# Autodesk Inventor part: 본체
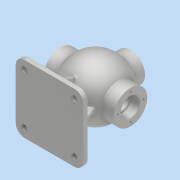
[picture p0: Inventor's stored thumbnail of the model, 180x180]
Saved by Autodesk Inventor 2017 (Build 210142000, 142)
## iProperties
Part Number: 본체
Material: 알루미늄 6061
Document SubType Name: Modeling
Designer: MRC
Density: 2.7 g/cm^3
Appearance: 알루미늄 - 평지
Mass: 1457.53 g
Surface Area: 1170.28 cm^2
Volume: 539.828 cm^3
Author: MRC
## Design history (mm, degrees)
sketch "스케치1"
  geometry: L1 (0, 53)-(0, -53); A1 r 53 centre (0, 0) between (0, -53) and (0, 53); 2 further points
  constraints: 2 coincident, 2 end point, 2 point on circle, 1 centre point, 1 midpoint, 1 vertical
  dimensions: "d2" = 106 diameter of A1
revolve "회전1" sketch "스케치1" stored, may be unused: angle "d3" = 90 deg
sketch "스케치2"
  geometry: L1 (0, 44)-(0, -44); A1 r 44 centre (0, 0) between (0, -44) and (0, 44); 2 further points
  constraints: 2 coincident, 2 end point, 2 point on circle, 1 centre point, 1 midpoint, 1 vertical
  dimensions: "d4" = 88 distance of L1.start L1.end
revolve "회전2" sketch "스케치2" stored, may be unused: angle "d5" = 90 deg
node "작업 평면1"
sketch "스케치3"
  geometry: C1 r 31 at (0, 0); 1 further point
  constraints: 1 centre point, 1 coincident
  dimensions: "d7" = 62 diameter of C1
extrude "돌출1" join sketch "스케치3" stored distance "d8" = 16; taper "d9" = 0 deg
sketch "스케치4"
  geometry: C1 r 17.5 at (0, 0); 1 further point
  constraints: 1 centre point, 1 coincident
  dimensions: "d10" = 35 diameter of C1
extrude "돌출2" cut sketch "스케치4" distance "d11" = 16; taper "d12" = 0 deg
sketch "스케치5"
  geometry: C1 r 15 at (0, 0); 1 further point
  constraints: 1 centre point, 1 coincident
  dimensions: "d13" = 30 diameter of C1
extrude "돌출3" cut sketch "스케치5" stored distance "d14" = 16; taper "d15" = 0 deg
fillet "모깎기1" dims "d16" = 0.6
chamfer "모따기1" distance "d17" = 1; stored, may be unused: second distance "d18" = 2, angle "d19" = 45 deg
sketch "스케치7"
  geometry: L1 (-62.5, -75)-(62.5, -75); L2 (62.5, -75)-(62.5, -85); L3 (62.5, -85)-(-62.5, -85); L4 (-62.5, -85)-(-62.5, -75); 2 further points
  constraints: 8 end point, 2 parallel, 1 horizontal, 1 midpoint, 1 perpendicular, 1 vertical alignment
  dimensions: "d20" = 125 distance of L1.start L1.end; "d21" = 10 distance of L1.end L2.end; "d22" = 85 distance from line of L3 point (0, 0)
extrude "돌출4" join sketch "스케치7" stored distance "d23" = 125; taper "d24" = 0 deg
sketch "스케치8"
  geometry: L1 (50.5, -75)-(39.971, -46.072); L2 (-50.5, -75)-(-41.337, -49.825); L3 (-62.5, -75)-(62.5, -75) reference; L4 (62.5, -75)-(62.5, -85) reference; L5 (-62.5, -85)-(-62.5, -75) reference; 1 further point
  constraints: 4 end point, 2 point on line
  dimensions: "d25" = 12 distance from line of L4 L1.start; "d26" = 12 distance of L3.start L2.start; "d28" = 20 deg angle of L1 L4; "d29" = 20 deg angle of L2 L5
feature "리브1" dims "d30" = 40, "d31" = 8, "d32" = 0, "d33" = 0, "d34" = 1, "d35" = 1
feature "리브2" dims "d36" = 40, "d37" = 8, "d38" = 0, "d39" = 0, "d40" = 1, "d41" = 1
sketch "스케치9"
  geometry: L1 (-75, 50.5)-(-46.657, 40.184); L2 (-75, -50.5)-(-48.7, -40.928); L3 (-75, -62.5)-(-85, -62.5) reference; L4 (-85, 62.5)-(-75, 62.5) reference; L5 (-85, 62.5)-(-85, -62.5) reference; L6 (-75, -62.5)-(-85, -62.5) reference; L7 (-75, 62.5)-(-75, -62.5) reference; L8 (-85, 62.5)-(-75, 62.5) reference; 1 further point
  constraints: 4 end point, 2 point on line
  dimensions: "d42" = 20 deg angle of L1 L4; "d43" = 20 deg angle of L2 L3; "d44" = 12 distance of L3.start L2.start; "d45" = 12 distance of L4.end L1.start
  node "투영된 루프1"
feature "리브3" dims "d46" = 40, "d47" = 8, "d48" = 0, "d49" = 0, "d50" = 1, "d51" = 1
feature "리브4" dims "d52" = 40, "d53" = 8, "d54" = 0, "d55" = 0, "d56" = 1, "d57" = 1
fillet "모깎기2" dims "d58" = 3
fillet "모깎기3" dims "d59" = 3
fillet "모깎기4" dims "d60" = 3
fillet "모깎기5" dims "d61" = 16
node "작업 평면2"
sketch "스케치10"
  geometry: C1 r 27 at (0, 0); 1 further point
  constraints: 1 centre point, 1 coincident
  dimensions: "d63" = 54 diameter of C1
extrude "돌출5" join sketch "스케치10" stored distance "d64" = 125; taper "d65" = 0 deg
sketch "스케치11"
  geometry: C1 r 13 at (0, 0); 1 further point
  constraints: 1 centre point, 1 coincident
  dimensions: "d66" = 26 diameter of C1
extrude "돌출6" cut sketch "스케치11" stored distance "d67" = 125; taper "d68" = 0 deg
fillet "모깎기6" dims "d69" = 3
sketch "스케치12"
  geometry: 2 further points
  constraints: 1 vertical alignment
  dimensions: "d70" = 24 distance of point (0, 0) point (0, 24)
hole "구멍1" sketch "스케치12" at (0, 24) diameter "d71" = 3.242; stored, may be unused: countersink angle "d75" = 90 deg, drill point angle "d77" = 118 deg; dims "d72" = 12, "d73" = 4, "d74" = 2, "d76" = 15
sketch "스케치13"
  geometry: 2 further points
  constraints: 1 vertical alignment
  dimensions: "d81" = 20 distance of point (0, 20) point (0, 0)
hole "구멍2" sketch "스케치13" at (0, 20) diameter "d82" = 3.242; stored, may be unused: countersink angle "d86" = 90 deg, drill point angle "d88" = 118 deg; dims "d83" = 9, "d84" = 4, "d85" = 2, "d87" = 11
sketch "스케치14"
  geometry: L1 (-16, 16)-(-16, 109) reference; L2 (93, 125)-(0, 125) reference; L3 (109, 16)-(109, 109) reference; L4 (0, 0)-(93, 0) reference; C1 r 5.5 at (0, 109); C2 r 5.5 at (0, 16); C3 r 5.5 at (93, 109); C4 r 5.5 at (93, 16); A1 r 16 centre (0, 16) between (-16, 16) and (0, 0) reference; A2 r 16 centre (0, 109) between (0, 125) and (-16, 109) reference; A3 r 16 centre (93, 109) between (109, 109) and (93, 125) reference; A4 r 16 centre (93, 16) between (93, 0) and (109, 16) reference; 1 further point
  constraints: 4 centre point, 4 coincident
  dimensions: "d92" = 11 diameter of C1; "d93" = 11 diameter of C2; "d94" = 11 diameter of C3; "d95" = 11 diameter of C4
extrude "돌출7" cut sketch "스케치14" distance "d96" = 125; taper "d97" = 0 deg
fillet "모깎기7" dims "d98" = 3
fillet "모깎기8" dims "d99" = 3
node "작업 평면3"
sketch "스케치15"
  geometry: L1 (1.621, 54)-(1.621, 65) reference; L2 (-27, 65)-(27, 65) reference; L3 (-27, 47.286)-(27, 47.286) reference; L4 (-42.113, 32.179)-(-42.113, -32.179) reference; L5 (-6.625, -40.411)-(-6.625, -52.165) reference; L6 (6.625, -52.165)-(6.625, -40.411) reference; L7 (38.307, -36.615)-(38.307, -36.615) reference; L8 (6.625, -40.411)-(6.625, -52.165) reference; L9 (-6.625, -52.165)-(-6.625, -40.411) reference; L10 (-38.307, -36.615)-(-38.307, -36.615) reference; L11 (42.113, -32.179)-(42.113, 32.179) reference; L12 (28.393, 44.753)-(-28.393, 44.753) reference; A1 r 52.584 centre (0, 0) between (-33.646, -40.411) and (-6.625, -52.165) reference; A2 r 52.584 centre (0, 0) between (6.625, -52.165) and (33.646, -40.411) reference; A3 r 52.584 centre (0, 0) between (6.625, -52.165) and (33.646, -40.411) reference; A4 r 52.584 centre (0, 0) between (-33.646, -40.411) and (-6.625, -52.165) reference; 8 further points; 2 other entities
  constraints: 1 vertical alignment, 11 other
  dimensions: "d101" = 9 distance from line of L2 point (0, 56)
feature "엠보싱1" sketch "스케치15" dims "d10" = 35, "d102" = 0.5, "d103" = 0
chamfer "모따기2" distance "d104" = 1; stored, may be unused: second distance "d105" = 2, angle "d106" = 45 deg
node "솔리드1"
mirror "미러1"
pattern_circular "원형 패턴1" dims angle "d79" = 360 deg
mirror "미러2"
pattern_circular "원형 패턴2" dims angle "d90" = 360 deg
node "투영된 루프2"
node "투영된 루프3"
node "투영된 루프4"
other parameters: "d6" = 65, "d62" = 65, "d100" = -27
